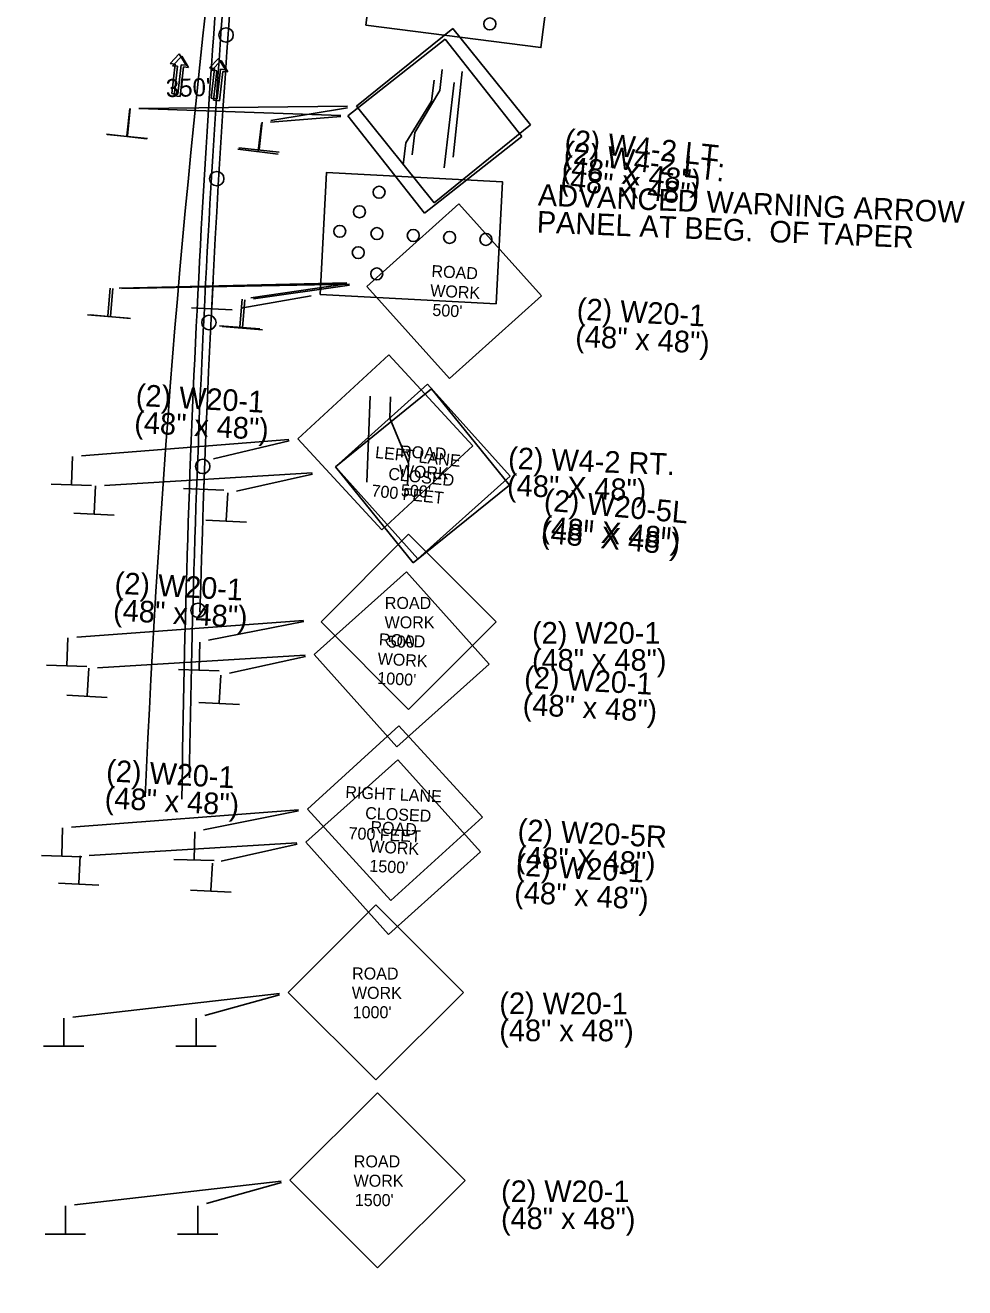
# Model space of a CAD drawing. Extents: x 659657 to 668193, y 633084 to 648639.
# Drawn here: x 661501 to 661762.1, y 640062.1 to 640412.7 of the extents above; entities that cross this region are included whole.
import ezdxf

# ---------------------------------------------------------------- set-up
doc = ezdxf.new("R2010")
doc.units = 0
for name, color, linetype in [('R_Border Prem', 7, 'Continuous'), ('R_Draft', 7, 'Continuous'), ('R_MOT_Stage 1B', 7, 'Continuous'), ('R_MOT_Stage 1B_Striping', 7, 'Continuous'), ('R_MOT_Stage 1C_Striping', 7, 'Continuous'), ('R_MOT_Stage 2_Striping_PPM', 7, 'Continuous'), ('R_MOT_Stage 3_Striping_PPM', 7, 'Continuous'), ('R_MOT_Stage 4_Striping_PPM', 7, 'Continuous'), ('R_MOT_Stage 5_Striping_PPM', 7, 'Continuous'), ('T_SIGNAL CONTROL CABINET', 7, 'Continuous'), ('TEMP_DETECTION ZONE_Stage 2', 7, 'Continuous'), ('TEMP_SIGNAL_HEAD_STAGE 2', 7, 'Continuous'), ('TEXT_TEMP_SIGNAL_POLES_STAGE 2', 7, 'Continuous')]:
    doc.layers.add(name, color=color, linetype=linetype)

msp = doc.modelspace()

# ---------------------------------------------------------------- linework, layer by layer
at = {"layer": 'R_Border Prem'}
msp.add_arc((665219.85, 639999.01), 3863.72, 156.12343, 201.98495, dxfattribs=at)
at = {"layer": 'R_Draft'}
for p, q in [((661612.79, 640313.06), (661587.17, 640290.11)), ((661635.74, 640287.45), (661612.79, 640313.06)), ((661523.04, 640284.94), (661580.72, 640288.42)), ((661580.78, 640288.03), (661559.71, 640283.36)), ((661610.13, 640264.52), (661587.17, 640290.11)), ((661635.74, 640287.45), (661610.13, 640264.52)), ((661520.13, 640277.12), (661520.54, 640284.79)), ((661556.85, 640275.15), (661557.27, 640282.82)), ((661525.71, 640276.66), (661514.48, 640277.26)), ((661562.43, 640274.68), (661551.19, 640275.3)), ((661606.91, 640260.88), (661581.3, 640237.93)), ((661629.86, 640235.27), (661606.91, 640260.88)), ((661521.11, 640234.3), (661578.8, 640237.78)), ((661604.25, 640212.34), (661581.3, 640237.93)), ((661578.85, 640237.39), (661557.79, 640232.73)), ((661629.86, 640235.27), (661604.25, 640212.34)), ((661518.21, 640226.48), (661518.62, 640234.15)), ((661554.92, 640224.52), (661555.34, 640232.18)), ((661523.79, 640226.02), (661512.56, 640226.62)), ((661560.5, 640224.05), (661549.27, 640224.66)), ((661604.57, 640208.74), (661578.96, 640185.79)), ((661627.52, 640183.13), (661604.57, 640208.74)), ((661518.78, 640182.16), (661576.46, 640185.64)), ((661576.52, 640185.25), (661555.45, 640180.59)), ((661601.91, 640160.2), (661578.96, 640185.79)), ((661515.87, 640174.34), (661516.28, 640182.01)), ((661627.52, 640183.13), (661601.91, 640160.2)), ((661552.59, 640172.38), (661553.01, 640180.04)), ((661521.45, 640173.88), (661510.22, 640174.48)), ((661558.17, 640171.91), (661546.93, 640172.52))]:
    msp.add_line(p, q, dxfattribs=at)
at = {"layer": 'R_MOT_Stage 1B'}
for centre in [(661556.8, 640410.04), (661554.2, 640370.12), (661552.03, 640330.17), (661550.31, 640290.2), (661549.02, 640250.22)]:
    msp.add_circle(centre, 2, dxfattribs=at)
for radius, end in [(3647.29, 179.20276), (3645.29, 178.47875)]:
    msp.add_arc((665193.55, 640152.91), radius, 174.74563, end, dxfattribs=at)
at = {"layer": 'R_MOT_Stage 1B_Striping'}
msp.add_arc((665193.55, 640152.91), 3649.29, 174.74563, 179.29562, dxfattribs=at)
at = {"layer": 'R_MOT_Stage 1C_Striping'}
for radius, start in [(3799.97, 157.70222), (3788.97, 157.70222), (3777.97, 163.39302)]:
    msp.add_arc((665219.85, 639999.01), radius, start, 174.95222, dxfattribs=at)
at = {"layer": 'R_MOT_Stage 2_Striping_PPM'}
for centre, radius, start, end in [((665219.85, 639999.01), 3798.72, 158.32294, 176.45222), ((665219.85, 639999.01), 3786.72, 158.32294, 176.45222), ((664866.31, 640052.27), 3335.18, 168.52205, 177.48815)]:
    msp.add_arc(centre, radius, start, end, dxfattribs=at)
at = {"layer": 'R_MOT_Stage 3_Striping_PPM'}
for centre, radius, start, end in [((665219.85, 639999.01), 3798.72, 158.32294, 176.45222), ((665219.85, 639999.01), 3786.72, 158.32294, 176.45222), ((664866.31, 640052.27), 3335.18, 168.52205, 177.48815)]:
    msp.add_arc(centre, radius, start, end, dxfattribs=at)
at = {"layer": 'R_MOT_Stage 4_Striping_PPM'}
for centre, radius, start, end in [((665219.85, 639999.01), 3798.72, 158.32294, 176.45222), ((665219.85, 639999.01), 3786.72, 158.32294, 176.45222), ((664866.31, 640052.27), 3335.18, 168.52205, 177.48815)]:
    msp.add_arc(centre, radius, start, end, dxfattribs=at)
at = {"layer": 'R_MOT_Stage 5_Striping_PPM'}
for centre, radius, start, end in [((665219.85, 639999.01), 3798.72, 158.32294, 176.45222), ((665219.85, 639999.01), 3786.72, 158.32294, 176.45222), ((664866.31, 640052.27), 3335.18, 168.52205, 177.48815)]:
    msp.add_arc(centre, radius, start, end, dxfattribs=at)
at = {"layer": 'T_SIGNAL CONTROL CABINET'}
for p, q in [((661541.24, 640402.13), (661543.81, 640404.78)), ((661541.92, 640401.5), (661544.48, 640404.15)), ((661543.81, 640404.78), (661545.71, 640401.63)), ((661544.48, 640404.15), (661546.39, 640401)), ((661552.17, 640400.9), (661554.74, 640403.55)), ((661552.85, 640400.28), (661555.41, 640402.93)), ((661554.74, 640403.55), (661556.64, 640400.4)), ((661555.41, 640402.93), (661557.32, 640399.78)), ((661541.24, 640402.13), (661542.64, 640401.97)), ((661542.64, 640401.97), (661541.71, 640393.75)), ((661541.92, 640401.5), (661543.31, 640401.34)), ((661543.31, 640401.34), (661542.4, 640393.12)), ((661544.32, 640401.78), (661543.39, 640393.56)), ((661544.99, 640401.15), (661544.07, 640392.93)), ((661544.32, 640401.78), (661545.71, 640401.63)), ((661544.99, 640401.15), (661546.39, 640401)), ((661552.17, 640400.9), (661553.57, 640400.74)), ((661553.57, 640400.74), (661552.64, 640392.52)), ((661552.85, 640400.28), (661554.25, 640400.12)), ((661554.25, 640400.12), (661553.33, 640391.9)), ((661555.25, 640400.55), (661554.32, 640392.33)), ((661555.92, 640399.93), (661555.01, 640391.71)), ((661555.25, 640400.55), (661556.64, 640400.4)), ((661555.92, 640399.93), (661557.32, 640399.78)), ((661541.71, 640393.75), (661543.39, 640393.56)), ((661542.4, 640393.12), (661544.07, 640392.93)), ((661552.64, 640392.52), (661554.32, 640392.33)), ((661553.33, 640391.9), (661555.01, 640391.71))]:
    msp.add_line(p, q, dxfattribs=at)
at = {"layer": 'TEMP_DETECTION ZONE_Stage 2'}
for p, q in [((661590.67, 640387.59), (661617.72, 640408.84)), ((661617.72, 640408.84), (661638.97, 640381.8)), ((661613.88, 640391.68), (661614.59, 640397.53)), ((661617.37, 640373.1), (661620.22, 640396.85)), ((661529.22, 640382), (661530.09, 640389.63)), ((661532.59, 640389.63), (661588.73, 640387.66)), ((661606.78, 640380.08), (661613.88, 640391.68)), ((661565.73, 640377.79), (661566.65, 640385.41)), ((661569.12, 640385.79), (661588.72, 640387.43)), ((661590.67, 640387.59), (661611.92, 640360.55)), ((661534.76, 640381.2), (661523.58, 640382.48)), ((661611.92, 640360.55), (661638.97, 640381.8)), ((661571.27, 640376.96), (661560.1, 640378.3)), ((661606.04, 640373.94), (661606.78, 640380.08)), ((661621.52, 640363.16), (661595.91, 640340.21)), ((661644.47, 640337.55), (661621.52, 640363.16)), ((661523.99, 640332.02), (661524.62, 640339.67)), ((661527.12, 640339.73), (661590.33, 640341.2)), ((661563.7, 640337.03), (661590.36, 640340.9)), ((661618.86, 640314.61), (661595.91, 640340.21)), ((661560.63, 640329.01), (661561.23, 640336.67)), ((661644.47, 640337.55), (661618.86, 640314.61)), ((661529.55, 640331.39), (661518.34, 640332.33)), ((661566.19, 640328.41), (661554.98, 640329.29)), ((661613.9, 640311.73), (661587.17, 640290.11)), ((661635.55, 640285.02), (661613.9, 640311.73)), ((661523.04, 640284.94), (661580.72, 640288.42)), ((661580.78, 640288.03), (661559.71, 640283.36)), ((661608.81, 640263.38), (661587.17, 640290.11)), ((661520.13, 640277.12), (661520.54, 640284.79)), ((661635.55, 640285.02), (661608.81, 640263.38)), ((661556.85, 640275.15), (661557.27, 640282.82)), ((661525.71, 640276.66), (661514.48, 640277.26)), ((661562.43, 640274.68), (661551.19, 640275.3)), ((661606.91, 640260.88), (661581.3, 640237.93)), ((661629.86, 640235.27), (661606.91, 640260.88)), ((661521.11, 640234.3), (661578.8, 640237.78)), ((661604.25, 640212.34), (661581.3, 640237.93)), ((661578.85, 640237.39), (661557.79, 640232.73)), ((661629.86, 640235.27), (661604.25, 640212.34)), ((661518.21, 640226.48), (661518.62, 640234.15)), ((661554.92, 640224.52), (661555.34, 640232.18)), ((661523.79, 640226.02), (661512.56, 640226.62)), ((661560.5, 640224.05), (661549.27, 640224.66)), ((661604.57, 640208.74), (661578.96, 640185.79)), ((661627.52, 640183.13), (661604.57, 640208.74)), ((661518.78, 640182.16), (661576.46, 640185.64)), ((661576.52, 640185.25), (661555.45, 640180.59)), ((661601.91, 640160.2), (661578.96, 640185.79)), ((661515.87, 640174.34), (661516.28, 640182.01)), ((661627.52, 640183.13), (661601.91, 640160.2)), ((661552.59, 640172.38), (661553.01, 640180.04)), ((661521.45, 640173.88), (661510.22, 640174.48)), ((661558.17, 640171.91), (661546.93, 640172.52))]:
    msp.add_line(p, q, dxfattribs=at)
msp.add_lwpolyline([(661648.58, 640440.17), (661599.99, 640446.4), (661595.67, 640412.78), (661644.27, 640406.55)], close=True, dxfattribs=at)
msp.add_circle((661630.09, 640413.1), 1.66, dxfattribs=at)
at = {"layer": 'TEMP_SIGNAL_HEAD_STAGE 2'}
for p, q in [((661593.01, 640390.24), (661619.79, 640411.82)), ((661619.79, 640411.82), (661641.37, 640385.04)), ((661616.17, 640394.61), (661616.8, 640400.47)), ((661619.88, 640376.08), (661622.44, 640399.86)), ((661609.21, 640382.93), (661616.17, 640394.61)), ((661529.41, 640381.99), (661530.19, 640389.63)), ((661532.69, 640389.66), (661590.53, 640390.22)), ((661569.26, 640386.27), (661590.56, 640389.83)), ((661593.01, 640390.24), (661614.59, 640363.46)), ((661565.97, 640378.23), (661566.8, 640385.86)), ((661614.59, 640363.46), (661641.37, 640385.04)), ((661534.96, 640381.26), (661523.77, 640382.4)), ((661608.55, 640376.78), (661609.21, 640382.93)), ((661571.52, 640377.47), (661560.34, 640378.67)), ((661621.52, 640363.16), (661595.91, 640340.21)), ((661644.47, 640337.55), (661621.52, 640363.16)), ((661524.71, 640331.94), (661525.38, 640339.59)), ((661527.88, 640339.64), (661591.1, 640340.83)), ((661564.45, 640336.77), (661591.12, 640340.53)), ((661618.86, 640314.61), (661595.91, 640340.21)), ((661561.34, 640328.77), (661561.97, 640336.43)), ((661644.47, 640337.55), (661618.86, 640314.61)), ((661530.27, 640331.29), (661519.07, 640332.27)), ((661566.9, 640328.15), (661555.69, 640329.08)), ((661613.9, 640311.73), (661587.17, 640290.11)), ((661635.55, 640285.02), (661613.9, 640311.73)), ((661523.04, 640284.94), (661580.72, 640288.42)), ((661580.78, 640288.03), (661559.71, 640283.36)), ((661608.81, 640263.38), (661587.17, 640290.11)), ((661520.13, 640277.12), (661520.54, 640284.79)), ((661635.55, 640285.02), (661608.81, 640263.38)), ((661556.85, 640275.15), (661557.27, 640282.82)), ((661525.71, 640276.66), (661514.48, 640277.26)), ((661562.43, 640274.68), (661551.19, 640275.3)), ((661606.91, 640260.88), (661581.3, 640237.93)), ((661629.86, 640235.27), (661606.91, 640260.88)), ((661521.11, 640234.3), (661578.8, 640237.78)), ((661604.25, 640212.34), (661581.3, 640237.93)), ((661578.85, 640237.39), (661557.79, 640232.73)), ((661629.86, 640235.27), (661604.25, 640212.34)), ((661518.21, 640226.48), (661518.62, 640234.15)), ((661554.92, 640224.52), (661555.34, 640232.18)), ((661523.79, 640226.02), (661512.56, 640226.62)), ((661560.5, 640224.05), (661549.27, 640224.66)), ((661604.57, 640208.74), (661578.96, 640185.79)), ((661627.52, 640183.13), (661604.57, 640208.74)), ((661518.78, 640182.16), (661576.46, 640185.64)), ((661576.52, 640185.25), (661555.45, 640180.59)), ((661601.91, 640160.2), (661578.96, 640185.79)), ((661515.87, 640174.34), (661516.28, 640182.01)), ((661627.52, 640183.13), (661601.91, 640160.2)), ((661552.59, 640172.38), (661553.01, 640180.04)), ((661521.45, 640173.88), (661510.22, 640174.48)), ((661558.17, 640171.91), (661546.93, 640172.52))]:
    msp.add_line(p, q, dxfattribs=at)
at = {"layer": 'TEXT_TEMP_SIGNAL_POLES_STAGE 2'}
for p, q in [((661552.86, 640334.18), (661553.24, 640341.85)), ((661560.91, 640334.17), (661580.43, 640337.56)), ((661558.45, 640333.74), (661547.21, 640334.29)), ((661576.74, 640297.85), (661601.98, 640321.19)), ((661601.98, 640321.19), (661625.33, 640295.96)), ((661595.92, 640285.83), (661596.85, 640309.73)), ((661602.29, 640303.62), (661602.52, 640309.51)), ((661607.48, 640291.06), (661602.29, 640303.62)), ((661516.6, 640293.15), (661574.27, 640297.66)), ((661576.74, 640297.85), (661600.09, 640272.61)), ((661553.32, 640292.27), (661574.33, 640297.27)), ((661600.09, 640272.61), (661625.33, 640295.96)), ((661513.85, 640285.28), (661514.11, 640292.95)), ((661550.59, 640284.02), (661550.89, 640291.69)), ((661607.24, 640284.87), (661607.48, 640291.06)), ((661519.44, 640284.93), (661508.2, 640285.3)), ((661556.17, 640283.64), (661544.93, 640284.07)), ((661607.53, 640271.34), (661583.18, 640247.04)), ((661631.82, 640246.99), (661607.53, 640271.34)), ((661515.29, 640242.81), (661578.35, 640247.4)), ((661551.95, 640241.92), (661578.39, 640247.1)), ((661607.48, 640222.72), (661583.18, 640247.04)), ((661631.82, 640246.99), (661607.48, 640222.72)), ((661512.53, 640234.95), (661512.79, 640242.63)), ((661549.28, 640233.76), (661549.5, 640241.43)), ((661518.12, 640234.6), (661506.88, 640234.98)), ((661554.87, 640233.43), (661543.62, 640233.76)), ((661604.85, 640218.16), (661579.42, 640195.02)), ((661628.01, 640192.76), (661604.85, 640218.16)), ((661513.89, 640189.96), (661576.93, 640194.83)), ((661550.56, 640189.23), (661576.97, 640194.53)), ((661602.58, 640169.6), (661579.42, 640195.02)), ((661628.01, 640192.76), (661602.58, 640169.6)), ((661511.17, 640182.1), (661511.39, 640189.77)), ((661547.92, 640181.06), (661548.11, 640188.74)), ((661516.76, 640181.77), (661505.52, 640182.1)), ((661553.51, 640180.76), (661542.27, 640181.04)), ((661598.43, 640168.42), (661574.09, 640144.12)), ((661622.73, 640144.08), (661598.43, 640168.42)), ((661514.2, 640137.26), (661571.61, 640143.84)), ((661571.69, 640143.45), (661550.9, 640137.66)), ((661598.39, 640119.8), (661574.09, 640144.12)), ((661622.73, 640144.08), (661598.39, 640119.8)), ((661511.72, 640129.3), (661511.71, 640136.98)), ((661548.48, 640129.31), (661548.49, 640136.99)), ((661517.31, 640129.14), (661506.06, 640129.13)), ((661554.08, 640129.14), (661542.83, 640129.15)), ((661598.91, 640116.23), (661574.56, 640091.93)), ((661623.2, 640091.89), (661598.91, 640116.23)), ((661514.67, 640085.07), (661572.08, 640091.65)), ((661572.16, 640091.26), (661551.37, 640085.47)), ((661598.86, 640067.61), (661574.56, 640091.93)), ((661623.2, 640091.89), (661598.86, 640067.61)), ((661512.19, 640077.11), (661512.18, 640084.79)), ((661548.95, 640077.12), (661548.96, 640084.8)), ((661517.78, 640076.95), (661506.53, 640076.94)), ((661554.55, 640076.95), (661543.3, 640076.96))]:
    msp.add_line(p, q, dxfattribs=at)
msp.add_lwpolyline([(661582.9, 640337.98), (661631.82, 640335.38), (661633.63, 640369.22), (661584.7, 640371.83)], close=True, dxfattribs=at)
for centre in [(661599.32, 640366.35), (661593.86, 640360.93), (661588.4, 640355.5), (661598.71, 640354.88), (661608.81, 640354.34), (661618.9, 640353.8), (661628.99, 640353.27), (661593.53, 640349.58), (661598.66, 640343.66)]:
    msp.add_circle(centre, 1.66, dxfattribs=at)

# ---------------------------------------------------------------- texts
at = {"layer": 'R_Draft'}
for s, height, rotation, p in [('(2) W20-1', 6, 356.865, (661531.59, 640307.06)), ('(48" x 48")', 6, 356.865, (661531.18, 640299.56)), ('ROAD', 3.339, 356.8654, (661605.06, 640292.72)), ('WORK', 3.339, 356.865, (661604.7, 640287.36)), ("500'", 3.339, 356.8655, (661605.31, 640281.94)), ('(2) W20-1', 6, 356.865, (661525.71, 640254.89)), ('(48" x 48")', 6, 356.865, (661525.3, 640247.39)), ('ROAD', 3.339, 356.8654, (661599.18, 640240.54)), ('WORK', 3.339, 356.865, (661598.83, 640235.18)), ("1000'", 3.339, 356.8655, (661598.75, 640229.8)), ('(2) W20-1', 6, 356.865, (661523.37, 640202.75)), ('(48" x 48")', 6, 356.865, (661522.96, 640195.25)), ('ROAD', 3.339, 356.8654, (661596.85, 640188.4)), ('WORK', 3.339, 356.865, (661596.49, 640183.04)), ("1500'", 3.339, 356.8655, (661596.55, 640177.65))]:
    msp.add_text(s, height=height, rotation=rotation, dxfattribs=at).set_placement(p)
at = {"layer": 'T_SIGNAL CONTROL CABINET'}
msp.add_text("350'", height=5, rotation=1.6349, dxfattribs=at).set_placement((661540.12, 640392.76))
at = {"layer": 'TEMP_DETECTION ZONE_Stage 2'}
for s, height, rotation, p in [('(2) W4-2 LT.', 6, 353.1567, (661650.42, 640374.65)), ('(48" X 48")', 6, 353.1567, (661649.53, 640367.19)), ('ROAD', 3.339, 356.8654, (661613.8, 640342.82)), ('WORK', 3.339, 356.865, (661613.44, 640337.46)), ('(2) W20-1', 6, 356.865, (661654.13, 640331.01)), ("500'", 3.339, 356.8655, (661614.05, 640332.04)), ('(48" x 48")', 6, 356.865, (661653.72, 640323.51)), ('LEFT LANE', 3.339, 353.9949, (661598.1, 640292.55)), ('CLOSED', 3.339, 353.9948, (661601.76, 640286.58)), ('700 FEET', 3.339, 353.994, (661597.08, 640281.87)), ('(2) W20-5L', 6, 354.7901, (661644.95, 640278)), ('(48" X 48")', 6, 354.7901, (661644.13, 640269.04)), ('ROAD', 3.339, 356.8654, (661599.18, 640240.54)), ('WORK', 3.339, 356.865, (661598.83, 640235.18)), ('(2) W20-1', 6, 356.865, (661639.52, 640228.73)), ("1000'", 3.339, 356.8655, (661598.75, 640229.8)), ('(48" x 48")', 6, 356.865, (661639.1, 640221.23)), ('ROAD', 3.339, 356.8654, (661596.85, 640188.4)), ('WORK', 3.339, 356.865, (661596.49, 640183.04)), ('(2) W20-1', 6, 356.865, (661637.18, 640176.59)), ("1500'", 3.339, 356.8655, (661596.55, 640177.65)), ('(48" x 48")', 6, 356.865, (661636.77, 640169.09))]:
    msp.add_text(s, height=height, rotation=rotation, dxfattribs=at).set_placement(p)
at = {"layer": 'TEMP_SIGNAL_HEAD_STAGE 2'}
for s, height, rotation, p in [('(2) W4-2 LT.', 6, 353.8614, (661650.67, 640378.01)), ('(48" X 48")', 6, 353.8614, (661649.87, 640370.54)), ('ROAD', 3.339, 356.8654, (661613.8, 640342.82)), ('WORK', 3.339, 356.865, (661613.44, 640337.46)), ('(2) W20-1', 6, 356.865, (661654.13, 640331.01)), ("500'", 3.339, 356.8655, (661614.05, 640332.04)), ('(48" x 48")', 6, 356.865, (661653.72, 640323.51)), ('LEFT LANE', 3.339, 353.9949, (661598.1, 640292.55)), ('CLOSED', 3.339, 353.9948, (661601.76, 640286.58)), ('700 FEET', 3.339, 353.994, (661597.08, 640281.87)), ('(2) W20-5L', 6, 354.7901, (661644.95, 640278)), ('(48" X 48")', 6, 354.7901, (661644.26, 640270.52)), ('ROAD', 3.339, 356.8654, (661599.18, 640240.54)), ('WORK', 3.339, 356.865, (661598.83, 640235.18)), ('(2) W20-1', 6, 356.865, (661639.52, 640228.73)), ("1000'", 3.339, 356.8655, (661598.75, 640229.8)), ('(48" x 48")', 6, 356.865, (661639.1, 640221.23)), ('ROAD', 3.339, 356.8654, (661596.85, 640188.4)), ('WORK', 3.339, 356.865, (661596.49, 640183.04)), ('(2) W20-1', 6, 356.865, (661637.18, 640176.59)), ("1500'", 3.339, 356.8655, (661596.55, 640177.65)), ('(48" x 48")', 6, 356.865, (661636.77, 640169.09))]:
    msp.add_text(s, height=height, rotation=rotation, dxfattribs=at).set_placement(p)
at = {"layer": 'TEXT_TEMP_SIGNAL_POLES_STAGE 2'}
for s, height, rotation, p in [('ADVANCED WARNING ARROW', 6, 357.6397, (661643.36, 640362.69)), ('PANEL AT BEG.  OF TAPER', 6, 357.6397, (661643.06, 640355.19)), ('(2) W4-2 RT.', 6, 357.7729, (661635.09, 640289.57)), ('(48" X 48")', 6, 357.7729, (661634.79, 640282.07)), ('ROAD', 3.339, 359.95, (661600.91, 640250.61)), ('WORK', 3.339, 359.9496, (661600.84, 640245.23)), ('(2) W20-1', 6, 359.9495, (661641.82, 640240.99)), ("500'", 3.339, 359.9501, (661601.74, 640239.86)), ('(48" x 48")', 6, 359.9495, (661641.81, 640233.47)), ('RIGHT LANE', 3.339, 357.3327, (661589.89, 640198.11)), ('CLOSED', 3.339, 357.3326, (661595.4, 640192.29)), ('(2) W20-5R', 6, 357.2323, (661637.71, 640186.3)), ('700 FEET', 3.339, 357.3318, (661590.77, 640186.7)), ('(48" X 48")', 6, 357.2323, (661637.35, 640178.8)), ('ROAD', 3.339, 359.95, (661591.82, 640147.69)), ('WORK', 3.339, 359.9496, (661591.75, 640142.32)), ('(2) W20-1', 6, 359.9495, (661632.73, 640138.07)), ("1000'", 3.339, 359.9501, (661591.97, 640136.94)), ('(48" x 48")', 6, 359.9495, (661632.72, 640130.56)), ('ROAD', 3.339, 359.95, (661592.29, 640095.5)), ('WORK', 3.339, 359.9496, (661592.22, 640090.13)), ('(2) W20-1', 6, 359.9495, (661633.2, 640085.88)), ("1500'", 3.339, 359.9501, (661592.57, 640084.75)), ('(48" x 48")', 6, 359.9495, (661633.19, 640078.37))]:
    msp.add_text(s, height=height, rotation=rotation, dxfattribs=at).set_placement(p)

doc.saveas('drawing.dxf')
